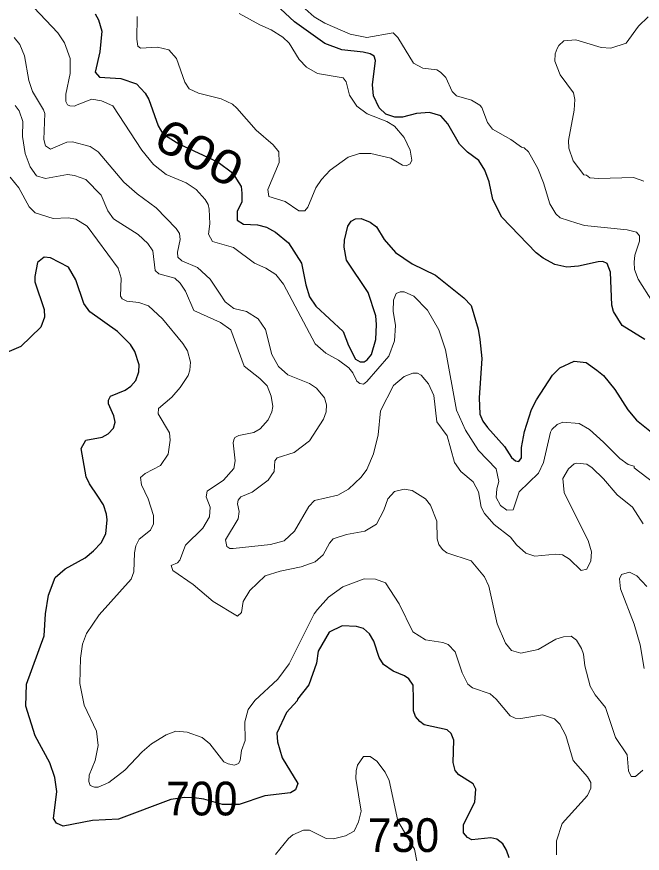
# Model space of a CAD drawing. Extents: x 294.2 to 320.3, y 7482.7 to 7510.7.
# Drawn here: x 299.342 to 300.826, y 7486.646 to 7488.63 of the extents above; entities that cross this region are included whole.
import ezdxf
from ezdxf.enums import TextEntityAlignment as Align

# ---------------------------------------------------------------- set-up
doc = ezdxf.new("R2010")
doc.units = 0
doc.header["$LTSCALE"] = 0.032
doc.layers.add('1', color=7, linetype='Continuous', lineweight=25)
doc.layers.add('2', color=7, linetype='Continuous', lineweight=13)
doc.layers.add('61', color=7, linetype='Continuous')

msp = doc.modelspace()

# ---------------------------------------------------------------- linework, layer by layer
at = {"layer": '1'}
for points in [[(300.8319, 7487.8646), (300.7783, 7487.8972), (300.7579, 7487.9304), (300.754, 7487.9457), (300.7508, 7488.0243), (300.7425, 7488.0447), (300.7325, 7488.0495), (300.7209, 7488.0485), (300.6749, 7488.0383), (300.6468, 7488.0357), (300.6187, 7488.0421), (300.5906, 7488.0568), (300.574, 7488.0702), (300.4929, 7488.1545), (300.4718, 7488.196), (300.4629, 7488.2382), (300.4527, 7488.2662), (300.4386, 7488.2892), (300.4111, 7488.3083), (300.3926, 7488.3275), (300.3645, 7488.3761), (300.348, 7488.3946), (300.3211, 7488.4029), (300.2905, 7488.4003), (300.2573, 7488.3914), (300.2387, 7488.3914), (300.2177, 7488.399), (300.2017, 7488.4137), (300.1883, 7488.4425), (300.1858, 7488.468), (300.1934, 7488.5261), (300.1902, 7488.5363), (300.1807, 7488.5421), (300.1641, 7488.5459), (300.113, 7488.5516), (300.0727, 7488.5663), (300.0012, 7488.618), (299.9355, 7488.6793)], [(299.5281, 7488.6366), (299.5364, 7488.6225), (299.5441, 7488.5957), (299.5396, 7488.5465), (299.5288, 7488.4987), (299.5384, 7488.4865), (299.5895, 7488.4833), (299.6265, 7488.4705), (299.6469, 7488.4489), (299.6558, 7488.4335), (299.6777, 7488.371), (299.6888, 7488.3517), (299.7271, 7488.3285), (299.8202, 7488.2847), (299.8541, 7488.2595), (299.8743, 7488.2272), (299.8765, 7488.211), (299.876, 7488.1906), (299.8654, 7488.1675), (299.8654, 7488.1476), (299.8804, 7488.1379), (299.9134, 7488.1363), (299.935, 7488.1304), (299.9561, 7488.1191), (299.9866, 7488.0932), (300.0179, 7488.0453), (300.0277, 7487.9938), (300.0366, 7487.9653), (300.0516, 7487.9433), (300.1162, 7487.883), (300.1289, 7487.8502), (300.1461, 7487.8174), (300.1572, 7487.8114), (300.1661, 7487.8114), (300.1738, 7487.8162), (300.1838, 7487.8286), (300.194, 7487.8641), (300.1957, 7487.8996), (300.194, 7487.9206), (300.1758, 7487.9761), (300.1248, 7488.0527), (300.119, 7488.0834), (300.1195, 7488.1001), (300.1273, 7488.1329), (300.1356, 7488.1447), (300.1456, 7488.1506), (300.1589, 7488.1512), (300.1805, 7488.1426), (300.1958, 7488.1318), (300.2141, 7488.1011), (300.2407, 7488.0705), (300.2798, 7488.0436), (300.3358, 7488.0167), (300.403, 7487.9629), (300.4203, 7487.9447), (300.4369, 7487.8888), (300.4403, 7487.8646), (300.4452, 7487.8195), (300.4394, 7487.7259), (300.4405, 7487.6872), (300.4477, 7487.6705), (300.4589, 7487.6554), (300.4988, 7487.6107)], [(299.5348, 7487.493), (299.5147, 7487.5218), (299.5071, 7487.5384), (299.4956, 7487.606), (299.5064, 7487.6252), (299.5453, 7487.6328), (299.5591, 7487.6409), (299.5719, 7487.6538), (299.5757, 7487.6684), (299.573, 7487.6834), (299.5601, 7487.7114), (299.5601, 7487.7205), (299.5651, 7487.7302), (299.5995, 7487.7442), (299.6127, 7487.7534), (299.6249, 7487.7674), (299.6316, 7487.7873), (299.6327, 7487.804), (299.6226, 7487.8359), (299.6124, 7487.8525), (299.5811, 7487.8831), (299.516, 7487.9297), (299.5013, 7487.9496), (299.4828, 7488.0058), (299.4649, 7488.0358), (299.4228, 7488.0581), (299.4074, 7488.0594), (299.3915, 7488.0466), (299.3851, 7488.0134), (299.3851, 7488.0012), (299.4075, 7487.9355), (299.4081, 7487.917), (299.3998, 7487.8933), (299.3519, 7487.848), (299.2753, 7487.8153)], [(300.5468, 7487.6457), (300.5635, 7487.6984), (300.5751, 7487.7215), (300.613, 7487.7795), (300.6302, 7487.7972), (300.6646, 7487.8129), (300.6927, 7487.8097), (300.7182, 7487.7919), (300.7336, 7487.7791), (300.7604, 7487.7459), (300.7913, 7487.6974), (300.8121, 7487.6727), (300.8515, 7487.6415)], [(300.4988, 7487.6107), (300.5155, 7487.5844), (300.5255, 7487.5768), (300.5332, 7487.5752), (300.5396, 7487.5833), (300.5396, 7487.6081), (300.5468, 7487.6457)], [(300.0088, 7486.8109), (300.0038, 7486.7964), (299.9916, 7486.7894), (299.9305, 7486.7818), (299.8698, 7486.7614), (299.8305, 7486.7616), (299.7861, 7486.774), (299.7631, 7486.7772), (299.7403, 7486.7778), (299.7075, 7486.7735), (299.5837, 7486.7268), (299.5218, 7486.7237), (299.4528, 7486.7102), (299.4368, 7486.7173), (299.4298, 7486.7281), (299.4375, 7486.7926), (299.4324, 7486.8258), (299.4206, 7486.8603), (299.3862, 7486.9243), (299.3643, 7486.9947), (299.3654, 7487.0469), (299.4075, 7487.1616), (299.4103, 7487.2138), (299.4177, 7487.2579), (299.4338, 7487.2999), (299.4576, 7487.3203), (299.5048, 7487.3461), (299.5248, 7487.3627), (299.5425, 7487.3821), (299.5541, 7487.4036), (299.5568, 7487.4364), (299.555, 7487.4503), (299.5484, 7487.4722), (299.5348, 7487.493)], [(300.5099, 7486.6347), (300.5041, 7486.653), (300.4952, 7486.668), (300.4808, 7486.6788), (300.4664, 7486.6826), (300.422, 7486.6777), (300.4112, 7486.6831), (300.4023, 7486.6944), (300.4018, 7486.7137), (300.4284, 7486.767), (300.4312, 7486.7977), (300.4251, 7486.8106), (300.3907, 7486.8316), (300.3818, 7486.8424), (300.3774, 7486.8607), (300.3793, 7486.9139), (300.3726, 7486.9301), (300.3632, 7486.9387), (300.3088, 7486.9505), (300.2985, 7486.9586), (300.288, 7486.9704), (300.2836, 7486.9838), (300.2836, 7487.0114), (300.2825, 7487.0442), (300.2725, 7487.0592), (300.2619, 7487.0668), (300.2353, 7487.0775), (300.2123, 7487.0936), (300.2017, 7487.1098), (300.189, 7487.149), (300.179, 7487.1663), (300.1646, 7487.1786), (300.148, 7487.1835), (300.1141, 7487.1851), (300.0833, 7487.17), (300.0574, 7487.1253), (300.053, 7487.0966), (300.0351, 7487.0455), (300.0082, 7487.0116)], [(300.0082, 7487.0116), (300.0076, 7487.0071), (299.9821, 7486.9797), (299.9594, 7486.9304), (299.9605, 7486.9099), (299.9716, 7486.8717), (300.0088, 7486.8109)]]:
    msp.add_lwpolyline(points, dxfattribs=at)
at = {"layer": '2'}
for points in [[(300.0504, 7487.8538), (299.9751, 7487.9955), (299.9572, 7488.0185), (299.933, 7488.0338), (299.9061, 7488.0453), (299.8563, 7488.0823), (299.8065, 7488.097), (299.797, 7488.1143), (299.8001, 7488.1386), (299.7988, 7488.173), (299.7963, 7488.1845), (299.7893, 7488.196), (299.7682, 7488.2202), (299.744, 7488.2362), (299.6967, 7488.256), (299.6667, 7488.279), (299.6392, 7488.3135), (299.5703, 7488.4182), (299.5435, 7488.4303), (299.5205, 7488.4342), (299.486, 7488.4207), (299.4796, 7488.4176), (299.4681, 7488.4188), (299.463, 7488.4207), (299.4586, 7488.4284), (299.4592, 7488.4463), (299.4694, 7488.4948), (299.4688, 7488.5306), (299.456, 7488.5676), (299.44, 7488.5919), (299.3685, 7488.6666)], [(300.0261, 7488.6487), (300.0478, 7488.6295), (300.0727, 7488.6142), (300.1334, 7488.5887), (300.173, 7488.5803), (300.2349, 7488.5918), (300.2458, 7488.5804), (300.2834, 7488.5197), (300.3058, 7488.5082), (300.339, 7488.5037), (300.3473, 7488.4986), (300.3601, 7488.4859), (300.3748, 7488.4527), (300.385, 7488.4424), (300.4207, 7488.4316), (300.4405, 7488.4201), (300.4456, 7488.4144), (300.459, 7488.3793), (300.4705, 7488.3633), (300.514, 7488.339), (300.5395, 7488.3205), (300.5459, 7488.3192), (300.5561, 7488.3097), (300.5778, 7488.2701), (300.5918, 7488.2356), (300.6065, 7488.1858), (300.6206, 7488.1622)], [(299.6284, 7488.6302), (299.6271, 7488.5765), (299.6297, 7488.5599), (299.636, 7488.5555), (299.6763, 7488.558), (299.7031, 7488.5516), (299.7209, 7488.5306), (299.7414, 7488.4743), (299.7516, 7488.4591), (299.7733, 7488.4482), (299.827, 7488.4348), (299.8544, 7488.4227), (299.8646, 7488.4131), (299.9106, 7488.3607), (299.9502, 7488.3256), (299.9636, 7488.3096), (299.9648, 7488.2841), (299.938, 7488.2203), (299.9406, 7488.2036), (299.9789, 7488.1915), (300.0114, 7488.1692), (300.0255, 7488.1692), (300.0325, 7488.1781), (300.0517, 7488.2241), (300.0651, 7488.2439), (300.0855, 7488.2656), (300.1283, 7488.2968), (300.1551, 7488.3058), (300.182, 7488.3052), (300.2292, 7488.2943), (300.2573, 7488.2777), (300.2662, 7488.2758), (300.2752, 7488.2809), (300.279, 7488.2899), (300.2751, 7488.3135), (300.2611, 7488.3435), (300.2381, 7488.3703), (300.2203, 7488.3811), (300.1736, 7488.3997), (300.1487, 7488.4176), (300.1315, 7488.4437), (300.1239, 7488.475), (300.1162, 7488.4846), (300.0555, 7488.4948), (300.0294, 7488.5101), (300.0121, 7488.528), (299.9885, 7488.5669), (299.9738, 7488.5816), (299.9457, 7488.5989), (299.9189, 7488.6104), (299.8697, 7488.6372)], [(300.8294, 7488.2401), (300.8051, 7488.2483), (300.7221, 7488.2458), (300.7017, 7488.2477), (300.6934, 7488.2541), (300.6876, 7488.2547), (300.662, 7488.288), (300.6519, 7488.3179), (300.6512, 7488.3365), (300.6646, 7488.408), (300.6659, 7488.4335), (300.6627, 7488.4495), (300.6314, 7488.4923), (300.6186, 7488.5248), (300.6193, 7488.5421), (300.6244, 7488.5548), (300.6276, 7488.5618), (300.6397, 7488.5727), (300.6685, 7488.5752), (300.7285, 7488.5567), (300.7515, 7488.5555), (300.7879, 7488.567), (300.8172, 7488.6071), (300.8396, 7488.6295)], [(299.3366, 7488.5804), (299.35, 7488.5638), (299.3608, 7488.537), (299.371, 7488.4782), (299.38, 7488.4527), (299.4062, 7488.4093), (299.4088, 7488.4003), (299.4068, 7488.339), (299.4107, 7488.3237), (299.4222, 7488.316), (299.4611, 7488.3326), (299.4745, 7488.3333), (299.5167, 7488.3218), (299.5358, 7488.309), (299.5965, 7488.2375), (299.6284, 7488.2094), (299.6731, 7488.1768), (299.7203, 7488.1277), (299.7286, 7488.1155), (299.7299, 7488.1015), (299.7235, 7488.0715), (299.7242, 7488.0594), (299.7343, 7488.0511), (299.7714, 7488.0351), (299.8008, 7488.0076), (299.8231, 7487.9738), (299.8371, 7487.954), (299.857, 7487.9374), (299.887, 7487.9304), (299.915, 7487.9132), (299.9323, 7487.8883), (299.947, 7487.8283), (299.9629, 7487.8001), (299.9853, 7487.7804), (300.0364, 7487.7599), (300.053, 7487.7491), (300.0721, 7487.7261), (300.0772, 7487.7095), (300.0759, 7487.6929), (300.0702, 7487.675), (300.0364, 7487.6239), (300.0006, 7487.5965), (299.9598, 7487.5837), (299.9546, 7487.5767), (299.9527, 7487.5511), (299.9387, 7487.5307), (299.901, 7487.502), (299.8736, 7487.4911), (299.8672, 7487.4835), (299.8659, 7487.4745), (299.8703, 7487.456), (299.8678, 7487.4388), (299.8378, 7487.389), (299.841, 7487.373), (299.848, 7487.3685), (299.8557, 7487.3685), (299.9444, 7487.3781), (299.977, 7487.3871), (300.0013, 7487.41), (300.0351, 7487.4681), (300.0485, 7487.4828), (300.104, 7487.4949), (300.129, 7487.509), (300.1596, 7487.5377), (300.1724, 7487.5563), (300.1883, 7487.5933), (300.1998, 7487.638), (300.2049, 7487.6954), (300.2362, 7487.7554), (300.2611, 7487.7765), (300.2815, 7487.7842), (300.293, 7487.7842), (300.3019, 7487.7797), (300.3186, 7487.7593)], [(299.3385, 7488.4195), (299.3481, 7488.4067), (299.357, 7488.3812), (299.3557, 7488.3454), (299.3621, 7488.3058), (299.3743, 7488.2739), (299.3889, 7488.2528), (299.4107, 7488.2458), (299.463, 7488.2554), (299.4796, 7488.2534), (299.5065, 7488.2439), (299.5428, 7488.2068), (299.5582, 7488.1692), (299.5722, 7488.1506), (299.6303, 7488.1136), (299.6533, 7488.0919), (299.6654, 7488.0747), (299.6705, 7488.0281), (299.6794, 7488.0204), (299.7177, 7488.0095), (299.7299, 7487.998), (299.7427, 7487.9789), (299.7624, 7487.9329), (299.8257, 7487.9048), (299.8499, 7487.887), (299.8818, 7487.8008), (299.9189, 7487.772), (299.9361, 7487.7542), (299.9457, 7487.7299), (299.9495, 7487.7057), (299.9476, 7487.6929), (299.9387, 7487.6737), (299.9195, 7487.652), (299.9049, 7487.6437), (299.8691, 7487.6367), (299.8595, 7487.6322), (299.8576, 7487.6265), (299.8557, 7487.6188), (299.8608, 7487.5767), (299.857, 7487.5582), (299.8327, 7487.5307), (299.7944, 7487.5045), (299.7918, 7487.4911), (299.8014, 7487.4669), (299.7995, 7487.4439), (299.7835, 7487.4171), (299.7427, 7487.3762), (299.729, 7487.3409), (299.7238, 7487.3348), (299.7089, 7487.3281), (299.7123, 7487.3164), (299.7605, 7487.283), (299.8082, 7487.2426), (299.8662, 7487.2081), (299.8754, 7487.217), (299.8794, 7487.2431), (299.8955, 7487.269), (299.9317, 7487.3034), (299.9674, 7487.3149), (300.0172, 7487.3251), (300.0504, 7487.3366), (300.0695, 7487.3539), (300.0842, 7487.3813), (300.0932, 7487.3915), (300.1245, 7487.4017), (300.1679, 7487.4094), (300.1954, 7487.4266), (300.2132, 7487.4592), (300.2228, 7487.486), (300.2381, 7487.5039), (300.2611, 7487.5096), (300.2802, 7487.5058), (300.3115, 7487.486), (300.3237, 7487.4713), (300.3384, 7487.4337), (300.3397, 7487.3915), (300.3435, 7487.3781), (300.3524, 7487.366), (300.362, 7487.3583), (300.4201, 7487.3391), (300.452, 7487.3015), (300.4616, 7487.2792), (300.482, 7487.1898), (300.5018, 7487.1438), (300.5159, 7487.1266), (300.5382, 7487.1202), (300.5791, 7487.1291)], [(299.327, 7488.249), (299.3475, 7488.2241), (299.3717, 7488.1788), (299.3864, 7488.1647), (299.4286, 7488.1513), (299.4643, 7488.1526), (299.4822, 7488.1494), (299.5096, 7488.1334), (299.583, 7488.0338), (299.5901, 7488.0096), (299.5888, 7487.9668), (299.5926, 7487.9604), (299.6035, 7487.9553), (299.6316, 7487.9521), (299.6546, 7487.9438), (299.6884, 7487.9131), (299.7363, 7487.8551), (299.7477, 7487.8372), (299.7541, 7487.8104), (299.7529, 7487.7918), (299.749, 7487.7785), (299.7299, 7487.7503), (299.7101, 7487.7273), (299.6788, 7487.7006), (299.6775, 7487.6878), (299.7043, 7487.6431), (299.7063, 7487.6252), (299.7012, 7487.592), (299.6833, 7487.5658), (299.6469, 7487.5467), (299.6361, 7487.5371), (299.6379, 7487.5192), (299.6539, 7487.486), (299.6667, 7487.4471), (299.6667, 7487.4273), (299.6597, 7487.4119), (299.6329, 7487.3909), (299.6252, 7487.3749), (299.6213, 7487.3583), (299.6201, 7487.3136), (299.6137, 7487.2958), (299.5377, 7487.2115), (299.5077, 7487.1668), (299.4987, 7487.1413), (299.4936, 7487.1081), (299.4924, 7487.048), (299.5026, 7486.997), (299.5319, 7486.9357), (299.5358, 7486.9012), (299.5281, 7486.8654), (299.5141, 7486.831), (299.5135, 7486.8156), (299.5166, 7486.8067), (299.5269, 7486.8022), (299.5358, 7486.8022), (299.5607, 7486.8137), (299.5984, 7486.8431), (299.6399, 7486.8865), (299.6622, 7486.905), (299.6967, 7486.9267), (299.7197, 7486.935), (299.7465, 7486.9331), (299.7822, 7486.9203), (299.8001, 7486.905), (299.8333, 7486.8628), (299.8436, 7486.8577), (299.8589, 7486.8546), (299.8685, 7486.859), (299.8723, 7486.866), (299.8754, 7486.8897), (299.8844, 7486.9133), (299.8831, 7486.9574)], [(300.6206, 7488.1622), (300.6314, 7488.1532), (300.671, 7488.1405), (300.6889, 7488.1347), (300.7898, 7488.1245), (300.8121, 7488.1187), (300.8191, 7488.1098)], [(300.8191, 7488.1098), (300.8191, 7488.0977), (300.8083, 7488.0645), (300.8063, 7488.0479), (300.8076, 7488.03), (300.816, 7488.007), (300.8504, 7487.954)], [(300.8536, 7487.5243), (300.807, 7487.5601), (300.8063, 7487.5639), (300.7923, 7487.5677), (300.7725, 7487.5824), (300.7342, 7487.6207), (300.7004, 7487.6507), (300.6761, 7487.6654), (300.6378, 7487.668), (300.6238, 7487.6629), (300.611, 7487.6507), (300.6084, 7487.6444), (300.5918, 7487.5729), (300.5797, 7487.5473), (300.5338, 7487.5026), (300.5197, 7487.4605), (300.505, 7487.4598), (300.4897, 7487.4707), (300.4794, 7487.4892), (300.4807, 7487.5103), (300.4858, 7487.5275), (300.4795, 7487.5575), (300.4373, 7487.601), (300.4067, 7487.6495), (300.3856, 7487.6967), (300.3594, 7487.8397), (300.3435, 7487.887), (300.3167, 7487.9342), (300.2841, 7487.9668), (300.2611, 7487.9776), (300.2515, 7487.9776), (300.2426, 7487.9731), (300.2362, 7487.9572), (300.2355, 7487.9317), (300.2407, 7487.8972), (300.2381, 7487.8615), (300.2247, 7487.8244), (300.173, 7487.765), (300.1647, 7487.7587), (300.1558, 7487.7599)], [(300.1558, 7487.7599), (300.1487, 7487.7657), (300.1392, 7487.7855), (300.1296, 7487.7969), (300.1053, 7487.8155), (300.0753, 7487.832), (300.0504, 7487.8538)], [(300.3186, 7487.7593), (300.3313, 7487.7312), (300.3384, 7487.6686), (300.3633, 7487.6354), (300.3805, 7487.5729), (300.3958, 7487.5512), (300.4252, 7487.5269)], [(300.4252, 7487.5269), (300.4373, 7487.5026), (300.4437, 7487.4669), (300.4514, 7487.4515), (300.4744, 7487.4254), (300.5133, 7487.3953), (300.5274, 7487.3775), (300.5497, 7487.3577), (300.5714, 7487.35), (300.6212, 7487.3551), (300.6366, 7487.3532), (300.6531, 7487.3436), (300.6812, 7487.3161), (300.6946, 7487.3194), (300.7042, 7487.3392), (300.7055, 7487.3609), (300.6972, 7487.3877), (300.6614, 7487.4592), (300.6403, 7487.5014), (300.6378, 7487.5346), (300.6512, 7487.5575), (300.6646, 7487.5697), (300.671, 7487.5709), (300.694, 7487.5684), (300.7074, 7487.5601), (300.7342, 7487.5339), (300.7661, 7487.4956), (300.8025, 7487.4669), (300.8281, 7487.4273)], [(300.8306, 7487.0838), (300.8208, 7487.1403), (300.807, 7487.1893), (300.7744, 7487.2728), (300.7719, 7487.297), (300.7764, 7487.3073), (300.7955, 7487.3123), (300.8127, 7487.304), (300.8364, 7487.2785)], [(300.0555, 7487.2242), (300.0817, 7487.253), (300.1156, 7487.2778), (300.1666, 7487.2964), (300.1935, 7487.2957), (300.2171, 7487.2874), (300.2496, 7487.237), (300.2815, 7487.1706), (300.3116, 7487.1521), (300.3531, 7487.1457), (300.3658, 7487.1412), (300.3818, 7487.1234), (300.3984, 7487.0736), (300.4124, 7487.0467), (300.4233, 7487.0385), (300.4648, 7487.0237), (300.4794, 7487.011), (300.5127, 7486.972), (300.5242, 7486.9663), (300.5382, 7486.965), (300.5893, 7486.9739), (300.6174, 7486.9644), (300.6301, 7486.9516), (300.6448, 7486.9248), (300.662, 7486.8654), (300.6959, 7486.8271), (300.7042, 7486.8137), (300.7042, 7486.8003), (300.6959, 7486.7824), (300.6359, 7486.716), (300.6225, 7486.6752), (300.6225, 7486.642)], [(299.8831, 7486.9574), (299.8914, 7486.9867), (299.9074, 7487.0078), (299.9617, 7487.0589), (299.9885, 7487.0953), (300.0478, 7487.214), (300.0555, 7487.2242)], [(300.5791, 7487.1291), (300.6212, 7487.1534), (300.6391, 7487.1591), (300.6576, 7487.1604), (300.6698, 7487.1508), (300.6819, 7487.1316), (300.6863, 7487.1183)], [(300.6863, 7487.1183), (300.6895, 7487.0902), (300.7023, 7487.0417), (300.7144, 7487.0212), (300.7387, 7486.9912), (300.7623, 7486.9203), (300.7897, 7486.8795), (300.793, 7486.8412), (300.7993, 7486.8278), (300.8095, 7486.8278), (300.8268, 7486.843)], [(299.9559, 7486.6432), (299.9866, 7486.6809), (299.9968, 7486.6892), (300.0223, 7486.7007), (300.0364, 7486.7007), (300.0766, 7486.6809), (300.0938, 7486.6796), (300.1219, 7486.6873), (300.1424, 7486.6981), (300.1532, 7486.7199), (300.1589, 7486.7454), (300.1468, 7486.8233), (300.1474, 7486.8412), (300.1506, 7486.8546), (300.1647, 7486.8756), (300.1807, 7486.875), (300.196, 7486.8641), (300.2164, 7486.8379), (300.226, 7486.8182), (300.2458, 7486.7224), (300.2859, 7486.6552), (300.2917, 7486.6228)]]:
    msp.add_lwpolyline(points, dxfattribs=at)

# ---------------------------------------------------------------- texts
at = {"layer": '61', "width": 1.2}
msp.add_text('600', height=0.08, rotation=332.203, dxfattribs=at).set_placement((299.7567, 7488.272), align=Align.CENTER)
at = {"layer": '61', "width": 0.95}
for s, p in [('700', (299.7812, 7486.7355)), ('730', (300.2594, 7486.6488))]:
    msp.add_text(s, height=0.08, dxfattribs=at).set_placement(p, align=Align.CENTER)

doc.saveas('drawing.dxf')
